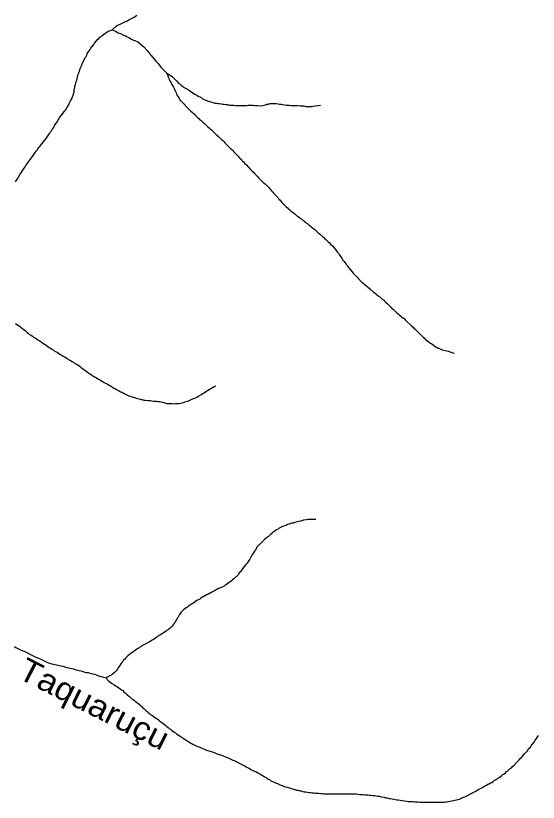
# Model space of a CAD drawing. Extents: x 652.3 to 678, y 7316.9 to 7344.9.
# Drawn here: x 664.343 to 666.148, y 7340.021 to 7342.739 of the extents above; entities that cross this region are included whole.
import ezdxf
from ezdxf.enums import TextEntityAlignment as Align

# ---------------------------------------------------------------- set-up
doc = ezdxf.new("R2010")
doc.units = 0
doc.header["$LTSCALE"] = 0.032
doc.layers.add('61', color=7, linetype='Continuous')
doc.layers.add('7', color=7, linetype='Continuous', lineweight=25)

msp = doc.modelspace()

# ---------------------------------------------------------------- linework, layer by layer
at = {"layer": '7'}
for points in [[(664.677, 7342.6909), (664.6898, 7342.7029), (664.6945, 7342.7061), (664.7017, 7342.7092), (664.7105, 7342.7132), (664.7152, 7342.7156), (664.72, 7342.718), (664.7248, 7342.7204), (664.7296, 7342.722), (664.7335, 7342.7252), (664.7526, 7342.7347), (664.7566, 7342.7379), (664.7614, 7342.7411)], [(664.3421, 7342.165), (664.3484, 7342.1745), (664.3516, 7342.1793), (664.354, 7342.1841), (664.3604, 7342.1936), (664.3635, 7342.1984), (664.3731, 7342.2127), (664.3755, 7342.2175), (664.3787, 7342.2215), (664.3818, 7342.2263), (664.385, 7342.231), (664.3914, 7342.239), (664.3978, 7342.2485), (664.4041, 7342.2565), (664.4105, 7342.266), (664.4137, 7342.2708), (664.4169, 7342.2748), (664.42, 7342.2788), (664.4232, 7342.2835), (664.4264, 7342.2875), (664.4296, 7342.2915), (664.4487, 7342.3154), (664.455, 7342.3249), (664.4614, 7342.3329), (664.4638, 7342.3377), (664.467, 7342.3416), (664.4694, 7342.3464), (664.4725, 7342.3512), (664.4757, 7342.3552), (664.4773, 7342.3599), (664.4805, 7342.3647), (664.4869, 7342.3727), (664.4893, 7342.3774), (664.4924, 7342.3822), (664.4948, 7342.387), (664.5076, 7342.4029), (664.5107, 7342.4077), (664.5147, 7342.4117), (664.5179, 7342.4164), (664.5203, 7342.4212), (664.5251, 7342.4307), (664.5282, 7342.4355), (664.5298, 7342.4403), (664.533, 7342.4451), (664.5378, 7342.4546), (664.5394, 7342.4594), (664.5418, 7342.4642), (664.5426, 7342.4697), (664.545, 7342.4745), (664.545, 7342.4801), (664.5458, 7342.4857), (664.5481, 7342.4904), (664.5481, 7342.496), (664.5497, 7342.5016), (664.5513, 7342.5063), (664.5521, 7342.5119), (664.5545, 7342.5167), (664.5553, 7342.5223), (664.5569, 7342.527), (664.5577, 7342.5326), (664.5593, 7342.5374), (664.5609, 7342.5421), (664.5633, 7342.5469), (664.5664, 7342.5565), (664.568, 7342.5612), (664.5704, 7342.566), (664.5736, 7342.5756), (664.576, 7342.5803), (664.5831, 7342.5947), (664.5863, 7342.5986), (664.5887, 7342.6034), (664.5903, 7342.6082), (664.5999, 7342.6225), (664.603, 7342.6273), (664.6062, 7342.6321), (664.6126, 7342.64), (664.6158, 7342.6448), (664.6221, 7342.6527), (664.6261, 7342.6567), (664.6301, 7342.6607), (664.6341, 7342.6647), (664.6381, 7342.6679), (664.642, 7342.671), (664.646, 7342.6742), (664.6508, 7342.6774), (664.6548, 7342.6806), (664.6587, 7342.6838), (664.6635, 7342.6862), (664.677, 7342.6909)], [(664.677, 7342.6909), (664.6882, 7342.6854), (664.6977, 7342.6806), (664.7049, 7342.6774), (664.716, 7342.6726), (664.7216, 7342.671), (664.7264, 7342.6679), (664.7359, 7342.6631), (664.7407, 7342.6599), (664.7502, 7342.6551), (664.755, 7342.6535), (664.7646, 7342.6488), (664.7693, 7342.6456), (664.7733, 7342.6424), (664.7773, 7342.6392), (664.7813, 7342.6352), (664.7853, 7342.6313), (664.7972, 7342.6193), (664.8004, 7342.6146), (664.8044, 7342.6106), (664.8075, 7342.6058), (664.8115, 7342.6018), (664.8274, 7342.5819), (664.8314, 7342.578), (664.8354, 7342.574), (664.8449, 7342.562), (664.8648, 7342.5413)], [(664.8648, 7342.5413), (664.8696, 7342.5286), (664.872, 7342.5238), (664.8736, 7342.5191), (664.876, 7342.5143), (664.8791, 7342.5095), (664.8823, 7342.5016), (664.8879, 7342.492), (664.8903, 7342.4872), (664.8927, 7342.4825), (664.8974, 7342.4729)], [(664.8648, 7342.5413), (664.8807, 7342.5318), (664.8847, 7342.5286), (664.8879, 7342.5246), (664.8919, 7342.5215), (664.8982, 7342.5143), (664.907, 7342.5055), (664.911, 7342.5024), (664.915, 7342.4992), (664.9189, 7342.496), (664.9229, 7342.4928), (664.9269, 7342.4896), (664.9364, 7342.4849), (664.9404, 7342.4817), (664.9452, 7342.4793), (664.95, 7342.4761), (664.9547, 7342.4729), (664.9595, 7342.4697), (664.9643, 7342.4673), (664.9691, 7342.4642), (664.9738, 7342.4618), (664.9786, 7342.4586), (664.9834, 7342.4562), (664.9874, 7342.453), (664.9921, 7342.4514), (665.0017, 7342.4467), (665.016, 7342.4419), (665.0216, 7342.4403), (665.0311, 7342.4371), (665.0367, 7342.4371), (665.0415, 7342.4355), (665.047, 7342.4355), (665.0582, 7342.4339), (665.0637, 7342.4339), (665.0693, 7342.4323), (665.0749, 7342.4323), (665.0797, 7342.4307), (665.0908, 7342.4307), (665.0964, 7342.43), (665.1019, 7342.4292), (665.1409, 7342.4292), (665.1465, 7342.43), (665.1632, 7342.43), (665.1688, 7342.4292), (665.1799, 7342.4292), (665.1911, 7342.4276), (665.1958, 7342.4292), (665.2014, 7342.43), (665.2062, 7342.4315), (665.2109, 7342.4331), (665.2165, 7342.4339), (665.2213, 7342.4355), (665.2436, 7342.4355), (665.2547, 7342.4339), (665.2603, 7342.4331), (665.2659, 7342.4323), (665.2714, 7342.4315), (665.277, 7342.4307), (665.2826, 7342.4307), (665.2881, 7342.43), (665.2937, 7342.4292), (665.316, 7342.4292), (665.3271, 7342.4276), (665.3383, 7342.4276), (665.3438, 7342.426), (665.3661, 7342.426), (665.3717, 7342.4268), (665.3772, 7342.4276), (665.3876, 7342.4292), (665.3955, 7342.4304), (665.3958, 7342.4304)], [(664.8974, 7342.4729), (664.899, 7342.4681), (664.9014, 7342.4634), (664.9078, 7342.4538), (664.9102, 7342.449), (664.9134, 7342.4451), (664.9253, 7342.4331), (664.9285, 7342.4292), (664.9325, 7342.4252), (664.9364, 7342.4212), (664.9484, 7342.4093), (664.9523, 7342.4061), (664.9563, 7342.4021), (664.9603, 7342.3989), (664.9643, 7342.3949), (664.9675, 7342.391), (664.9714, 7342.387), (664.9754, 7342.3838), (664.9794, 7342.3798), (664.9834, 7342.3766), (664.9874, 7342.3735), (664.9913, 7342.3695), (664.9953, 7342.3663), (664.9993, 7342.3631), (665.0073, 7342.3552), (665.0112, 7342.352), (665.0152, 7342.348), (665.0192, 7342.3448), (665.0271, 7342.3369), (665.0311, 7342.3337), (665.0343, 7342.3297), (665.0383, 7342.3265), (665.0423, 7342.3225), (665.0462, 7342.3194), (665.0542, 7342.3114), (665.0582, 7342.3082), (665.0622, 7342.3042), (665.0653, 7342.3003), (665.0852, 7342.2804), (665.0892, 7342.2772), (665.0932, 7342.2732), (665.0964, 7342.2692), (665.1043, 7342.2613), (665.1075, 7342.2573), (665.1115, 7342.2533), (665.1155, 7342.2493), (665.1186, 7342.2454), (665.1226, 7342.2422), (665.1258, 7342.2374), (665.1298, 7342.2342), (665.1338, 7342.2302), (665.1417, 7342.2223), (665.1449, 7342.2183), (665.1489, 7342.2143), (665.1521, 7342.2103), (665.16, 7342.2024), (665.164, 7342.1984), (665.168, 7342.1944), (665.1743, 7342.1865), (665.1783, 7342.1833), (665.1815, 7342.1793), (665.1974, 7342.1634), (665.2014, 7342.1602), (665.2054, 7342.157), (665.2173, 7342.1451), (665.2205, 7342.1411), (665.2245, 7342.1371), (665.2277, 7342.1332), (665.2316, 7342.1292), (665.2348, 7342.1252), (665.2428, 7342.1172), (665.246, 7342.1133), (665.2491, 7342.1093), (665.2523, 7342.1053), (665.2563, 7342.1013), (665.2627, 7342.0934), (665.2666, 7342.0894), (665.2706, 7342.0862), (665.2738, 7342.0822), (665.2778, 7342.0783), (665.2818, 7342.0751), (665.2857, 7342.0711), (665.2897, 7342.0679), (665.2937, 7342.0647), (665.2985, 7342.0615), (665.3025, 7342.0584), (665.3064, 7342.0552), (665.3104, 7342.0512), (665.3144, 7342.048), (665.3192, 7342.0448), (665.3231, 7342.0417), (665.3279, 7342.0385), (665.3319, 7342.0353), (665.3359, 7342.0321), (665.3398, 7342.0289), (665.3438, 7342.0257), (665.3478, 7342.0226), (665.3518, 7342.0194), (665.3558, 7342.0162), (665.3597, 7342.013), (665.3637, 7342.0098)], [(665.3637, 7342.0098), (665.3677, 7342.0066), (665.3717, 7342.0035), (665.3757, 7342.0003), (665.3796, 7341.9971), (665.3876, 7341.9891), (665.3916, 7341.986), (665.3955, 7341.9828), (665.3995, 7341.9796), (665.4035, 7341.9756), (665.4075, 7341.9724), (665.4107, 7341.9685), (665.4146, 7341.9653), (665.4226, 7341.9573), (665.4266, 7341.9541), (665.4306, 7341.9502), (665.4385, 7341.9422), (665.4544, 7341.9223), (665.4576, 7341.9183), (665.4608, 7341.9136), (665.4703, 7341.8992), (665.4735, 7341.8945), (665.4767, 7341.8905), (665.4799, 7341.8865), (665.4831, 7341.8817), (665.4863, 7341.8777), (665.4894, 7341.8738), (665.5085, 7341.8499), (665.5125, 7341.8459), (665.5165, 7341.8419), (665.5197, 7341.838), (665.5237, 7341.8348), (665.5268, 7341.83), (665.5388, 7341.8181), (665.5427, 7341.8149), (665.5467, 7341.8109), (665.5515, 7341.8077), (665.5555, 7341.8045), (665.5595, 7341.8006), (665.5634, 7341.7974), (665.5674, 7341.7934), (665.5714, 7341.7902), (665.5754, 7341.787), (665.5794, 7341.7839), (665.5841, 7341.7807), (665.5881, 7341.7767), (665.5921, 7341.7735), (665.5961, 7341.7703), (665.6008, 7341.7671), (665.6048, 7341.7632), (665.6088, 7341.76), (665.6128, 7341.7568), (665.6167, 7341.7528), (665.6207, 7341.7496), (665.6247, 7341.7457), (665.6287, 7341.7425), (665.6366, 7341.7345), (665.6398, 7341.7305), (665.6438, 7341.7266), (665.6478, 7341.7234), (665.6557, 7341.7154), (665.6597, 7341.7122), (665.6637, 7341.7091), (665.6677, 7341.7051), (665.6717, 7341.7019), (665.6756, 7341.6987), (665.6796, 7341.6955), (665.6844, 7341.6923), (665.6884, 7341.6884), (665.6915, 7341.6844), (665.6955, 7341.6812), (665.7075, 7341.6693), (665.7114, 7341.6661), (665.7154, 7341.6629), (665.7186, 7341.6589), (665.7226, 7341.6557), (665.7425, 7341.6359), (665.7464, 7341.6319), (665.7504, 7341.6279), (665.7544, 7341.6247), (665.7584, 7341.6207), (665.7624, 7341.6176), (665.7663, 7341.6144), (665.7703, 7341.6112), (665.7751, 7341.608), (665.7799, 7341.6048), (665.7846, 7341.6016), (665.7886, 7341.5985), (665.7926, 7341.5953), (665.7974, 7341.5937), (665.8021, 7341.5905), (665.8069, 7341.5889), (665.8117, 7341.5865), (665.8165, 7341.5849), (665.8212, 7341.5833), (665.8268, 7341.5825), (665.8316, 7341.581), (665.8364, 7341.5794), (665.8523, 7341.5746), (665.8568, 7341.5732), (665.8572, 7341.5731)], [(664.3413, 7341.6756), (664.346, 7341.6733), (664.3508, 7341.6701), (664.3556, 7341.6669), (664.3596, 7341.6637), (664.3635, 7341.6605), (664.3675, 7341.6573), (664.3715, 7341.6542), (664.3755, 7341.651), (664.3795, 7341.6478), (664.3834, 7341.6446), (664.3874, 7341.6406), (664.3914, 7341.6374), (664.3962, 7341.6351), (664.4009, 7341.6319), (664.4049, 7341.6287), (664.4145, 7341.6239), (664.4184, 7341.6207), (664.4224, 7341.6176), (664.4272, 7341.6152), (664.4312, 7341.612), (664.4359, 7341.6088), (664.4407, 7341.6056), (664.4455, 7341.6024), (664.4495, 7341.5993), (664.4542, 7341.5961), (664.459, 7341.5929), (664.463, 7341.5897), (664.4678, 7341.5865), (664.4725, 7341.5841), (664.4765, 7341.581), (664.4813, 7341.5786), (664.4861, 7341.5762)], [(664.4861, 7341.5762), (664.4908, 7341.573), (664.4956, 7341.5698), (664.5004, 7341.5666), (664.5052, 7341.5634), (664.5147, 7341.5587), (664.5195, 7341.5555), (664.5235, 7341.5523), (664.533, 7341.5475), (664.5378, 7341.5444), (664.5426, 7341.542), (664.5465, 7341.5388), (664.5513, 7341.5364), (664.5561, 7341.5332), (664.5609, 7341.53), (664.5656, 7341.5268), (664.5696, 7341.5237), (664.5736, 7341.5205), (664.5776, 7341.5173), (664.5816, 7341.5141), (664.5863, 7341.5109), (664.5911, 7341.5077), (664.5951, 7341.5038), (664.5999, 7341.5014), (664.6046, 7341.4982), (664.6086, 7341.495), (664.6134, 7341.4934), (664.6174, 7341.4902), (664.6221, 7341.4879), (664.6269, 7341.4847), (664.6317, 7341.4815), (664.6365, 7341.4791), (664.6404, 7341.4759), (664.6452, 7341.4743), (664.6492, 7341.4711), (664.6587, 7341.4664), (664.6635, 7341.4632), (664.6731, 7341.4584), (664.6778, 7341.4552), (664.6818, 7341.4521), (664.6866, 7341.4505), (664.6914, 7341.4473), (664.6961, 7341.4449), (664.7009, 7341.4425), (664.7057, 7341.4393), (664.7105, 7341.4377), (664.7152, 7341.4345), (664.72, 7341.4322), (664.7248, 7341.4298), (664.7296, 7341.4282), (664.7343, 7341.4258), (664.7487, 7341.421), (664.7542, 7341.4194), (664.759, 7341.4178), (664.7638, 7341.4162), (664.7693, 7341.4147), (664.7749, 7341.4131), (664.7805, 7341.4123), (664.7853, 7341.4107), (664.7908, 7341.4107), (664.802, 7341.4091), (664.8075, 7341.4091), (664.8131, 7341.4083), (664.8187, 7341.4075), (664.8298, 7341.4075), (664.8346, 7341.4059), (664.8402, 7341.4059), (664.8457, 7341.4051), (664.8505, 7341.4035), (664.8561, 7341.4019), (664.8608, 7341.4003), (664.8664, 7341.3995), (664.872, 7341.3995), (664.8776, 7341.3987), (664.8839, 7341.3987), (664.8895, 7341.3979), (664.8951, 7341.3987), (664.9014, 7341.3987), (664.907, 7341.3995), (664.9126, 7341.4003), (664.9181, 7341.4011), (664.9229, 7341.4027), (664.9277, 7341.4043), (664.9372, 7341.4075), (664.9428, 7341.4091), (664.9571, 7341.4162), (664.9619, 7341.4178), (664.9667, 7341.4202), (664.9714, 7341.4218), (664.9754, 7341.425), (664.985, 7341.4298), (664.9897, 7341.433), (664.9945, 7341.4361), (664.9993, 7341.4393), (665.0033, 7341.4425), (665.008, 7341.4449), (665.012, 7341.4481), (665.0168, 7341.4505), (665.0311, 7341.4584), (665.0339, 7341.46), (665.0343, 7341.4602)], [(665.3796, 7340.9985), (665.3589, 7340.9985), (665.3534, 7340.9977), (665.3478, 7340.9969), (665.3367, 7340.9953), (665.3271, 7340.9921), (665.3215, 7340.9913), (665.312, 7340.9882), (665.3064, 7340.9874), (665.3017, 7340.9858), (665.2961, 7340.985), (665.2865, 7340.9818), (665.2818, 7340.9802), (665.277, 7340.9778), (665.2722, 7340.9762), (665.2674, 7340.9746), (665.2579, 7340.9699), (665.2531, 7340.9683), (665.2491, 7340.9651), (665.2444, 7340.9627), (665.2404, 7340.9595), (665.2356, 7340.9563), (665.2316, 7340.9532), (665.2277, 7340.95), (665.2237, 7340.946), (665.2197, 7340.9428), (665.2157, 7340.9396), (665.2117, 7340.9364), (665.2078, 7340.9333), (665.2038, 7340.9301), (665.1879, 7340.9142), (665.1839, 7340.911), (665.1775, 7340.903), (665.1712, 7340.8935), (665.168, 7340.8887), (665.1616, 7340.8792), (665.1584, 7340.8752), (665.1537, 7340.8656), (665.1513, 7340.8609)], [(665.1513, 7340.8609), (665.1489, 7340.8561), (665.1425, 7340.8465), (665.1385, 7340.8426), (665.1258, 7340.8266), (665.1194, 7340.8171), (665.1155, 7340.8131), (665.1123, 7340.8083), (665.0964, 7340.7924), (665.0924, 7340.7892), (665.0884, 7340.7861), (665.0844, 7340.7829), (665.0805, 7340.7797), (665.0757, 7340.7765), (665.0717, 7340.7733), (665.0669, 7340.7709), (665.0629, 7340.7678), (665.0486, 7340.7606), (665.0439, 7340.759), (665.0295, 7340.7518), (665.0256, 7340.7487), (665.0208, 7340.7471), (665.016, 7340.7439), (665.0112, 7340.7423), (665.0065, 7340.7391), (665.0017, 7340.7375), (664.9969, 7340.7343), (664.9921, 7340.7312), (664.9874, 7340.7296), (664.9826, 7340.7264), (664.9786, 7340.7232), (664.9738, 7340.7208), (664.9691, 7340.7176), (664.9643, 7340.7144), (664.9595, 7340.7113), (664.9547, 7340.7081), (664.95, 7340.7049), (664.9452, 7340.7017), (664.9404, 7340.6985), (664.9364, 7340.6954), (664.9325, 7340.6922), (664.9277, 7340.689), (664.9229, 7340.6858), (664.915, 7340.6778), (664.9086, 7340.6699), (664.907, 7340.6651), (664.9038, 7340.6603), (664.9006, 7340.6564), (664.8982, 7340.6516), (664.8951, 7340.6468), (664.8927, 7340.642), (664.8895, 7340.6373), (664.8863, 7340.6333), (664.8831, 7340.6285), (664.8791, 7340.6245), (664.8752, 7340.6214), (664.8712, 7340.6182), (664.8664, 7340.615), (664.8624, 7340.6118), (664.8577, 7340.6086), (664.8529, 7340.6054), (664.8481, 7340.6023), (664.8433, 7340.5999), (664.8394, 7340.5967), (664.8346, 7340.5943), (664.8306, 7340.5911), (664.8258, 7340.5879), (664.8211, 7340.5848), (664.8171, 7340.5816), (664.8123, 7340.5792), (664.8075, 7340.5768), (664.8028, 7340.5736), (664.7932, 7340.5688), (664.7884, 7340.5657), (664.7837, 7340.5641), (664.7789, 7340.5609), (664.7749, 7340.5577), (664.7701, 7340.5553), (664.7662, 7340.5521), (664.7614, 7340.5497), (664.7574, 7340.5466), (664.7526, 7340.5434), (664.7487, 7340.5402), (664.7439, 7340.537), (664.7391, 7340.5338), (664.7351, 7340.5298), (664.7311, 7340.5267), (664.7272, 7340.5235), (664.7232, 7340.5195), (664.72, 7340.5155), (664.716, 7340.5123), (664.7136, 7340.5076), (664.7097, 7340.5036), (664.7065, 7340.4996), (664.7001, 7340.4901), (664.6969, 7340.4853), (664.6945, 7340.4805), (664.6914, 7340.4765), (664.685, 7340.4694), (664.6754, 7340.4614), (664.6548, 7340.4503)], [(664.3397, 7340.5593), (664.3436, 7340.5561), (664.3484, 7340.5537), (664.3532, 7340.5505), (664.358, 7340.5489), (664.3675, 7340.5442), (664.3723, 7340.5426), (664.4009, 7340.5283), (664.4057, 7340.5259), (664.4153, 7340.5211), (664.42, 7340.5195), (664.4296, 7340.5147), (664.4344, 7340.5131), (664.4535, 7340.5036), (664.463, 7340.5004), (664.4678, 7340.4988), (664.4733, 7340.498), (664.4789, 7340.4964), (664.4845, 7340.4956), (664.4893, 7340.494), (664.5004, 7340.4925), (664.506, 7340.4909), (664.5155, 7340.4877), (664.5211, 7340.4869), (664.5267, 7340.4853), (664.5314, 7340.4837), (664.537, 7340.4829), (664.5426, 7340.4813), (664.5473, 7340.4797), (664.5521, 7340.4781), (664.5577, 7340.4773), (664.5625, 7340.4757), (664.568, 7340.4749), (664.5728, 7340.4734), (664.5824, 7340.4702), (664.5879, 7340.4694), (664.5935, 7340.4686), (664.5991, 7340.467), (664.6038, 7340.4654), (664.6094, 7340.4646), (664.615, 7340.463), (664.6245, 7340.4598), (664.6293, 7340.4582), (664.6388, 7340.4551), (664.6548, 7340.4503)], [(664.6548, 7340.4503), (664.6651, 7340.4391), (664.6699, 7340.436), (664.6747, 7340.4328), (664.6818, 7340.428), (664.6906, 7340.4224), (664.6953, 7340.4192), (664.6993, 7340.4161), (664.7041, 7340.4129)], [(664.7041, 7340.4129), (664.7081, 7340.4097), (664.7128, 7340.4065), (664.7168, 7340.4025), (664.7208, 7340.3986), (664.7248, 7340.3954), (664.7288, 7340.3922), (664.7327, 7340.389), (664.7367, 7340.3858), (664.7407, 7340.3819), (664.7447, 7340.3787), (664.7494, 7340.3755), (664.7534, 7340.3723), (664.7574, 7340.3691), (664.7614, 7340.3659), (664.7654, 7340.3628), (664.7693, 7340.3596), (664.7733, 7340.3556), (664.7773, 7340.3524), (664.7813, 7340.3484), (664.7853, 7340.3452), (664.7892, 7340.3413), (664.7932, 7340.3373), (664.7972, 7340.3341), (664.8012, 7340.3309), (664.8051, 7340.3269), (664.8091, 7340.3238), (664.8139, 7340.3214), (664.8179, 7340.3182), (664.8227, 7340.315), (664.8274, 7340.3118), (664.8314, 7340.3086), (664.8362, 7340.3055), (664.8402, 7340.3023), (664.8441, 7340.2991), (664.8481, 7340.2959), (664.8529, 7340.2927), (664.8569, 7340.2896), (664.8616, 7340.2864), (664.8656, 7340.2824), (664.8696, 7340.2792), (664.8736, 7340.276), (664.8776, 7340.2728), (664.8815, 7340.2697), (664.8855, 7340.2665), (664.8903, 7340.2633), (664.8951, 7340.2601), (664.899, 7340.2569), (664.9038, 7340.2537), (664.9086, 7340.2506), (664.9134, 7340.2474), (664.9173, 7340.2442), (664.9221, 7340.2418), (664.9261, 7340.2386), (664.9309, 7340.2362), (664.9356, 7340.2331), (664.9404, 7340.2307), (664.9452, 7340.2275), (664.95, 7340.2243), (664.9691, 7340.2148), (664.9786, 7340.2116), (664.9882, 7340.2068), (664.9929, 7340.2052), (664.9977, 7340.2028), (665.0025, 7340.2012), (665.0073, 7340.1996), (665.0216, 7340.1949), (665.0263, 7340.1933), (665.0311, 7340.1917), (665.0359, 7340.1893), (665.0454, 7340.1861), (665.0502, 7340.1845), (665.0598, 7340.1813), (665.0645, 7340.179), (665.0693, 7340.1774), (665.0741, 7340.175), (665.0789, 7340.1734), (665.0932, 7340.1662), (665.098, 7340.1646), (665.1266, 7340.1503), (665.1314, 7340.1479), (665.1362, 7340.1455), (665.1409, 7340.1423), (665.1505, 7340.1376), (665.1552, 7340.1344), (665.1696, 7340.1272), (665.1743, 7340.1256), (665.1791, 7340.1225), (665.1887, 7340.1177), (665.1934, 7340.1145), (665.1982, 7340.1121), (665.2022, 7340.1089), (665.207, 7340.1073), (665.2109, 7340.1042), (665.2149, 7340.101), (665.2197, 7340.0994), (665.2237, 7340.0962), (665.2428, 7340.0867), (665.2475, 7340.0851), (665.2523, 7340.0827), (665.2571, 7340.0811)], [(666.0257, 7340.1161), (666.0297, 7340.1193), (666.0345, 7340.1225), (666.0385, 7340.1264), (666.0432, 7340.1296), (666.0472, 7340.1336), (666.0512, 7340.1368), (666.0552, 7340.14), (666.0592, 7340.1439), (666.0631, 7340.1479), (666.0751, 7340.1599), (666.0782, 7340.1638), (666.0822, 7340.1678), (666.0854, 7340.1718), (666.0894, 7340.1758), (666.0934, 7340.1797), (666.0997, 7340.1877), (666.1037, 7340.1909), (666.1069, 7340.1949), (666.1101, 7340.1988), (666.1133, 7340.2036), (666.1164, 7340.2076), (666.1204, 7340.2116), (666.1236, 7340.2156), (666.1268, 7340.2203), (666.1332, 7340.2283), (666.1363, 7340.2331), (666.1395, 7340.2378), (666.1459, 7340.2474), (666.1483, 7340.2522)], [(665.2571, 7340.0811), (665.2619, 7340.0787), (665.2714, 7340.0755), (665.2762, 7340.0739), (665.281, 7340.0723), (665.2921, 7340.0691), (665.2977, 7340.0676), (665.3032, 7340.066), (665.3128, 7340.0628), (665.3184, 7340.062), (665.3239, 7340.0604), (665.3295, 7340.0596), (665.3343, 7340.058), (665.3398, 7340.0572), (665.3454, 7340.0564), (665.351, 7340.0556), (665.3574, 7340.0548), (665.3629, 7340.0548), (665.3685, 7340.0532), (665.3741, 7340.0532), (665.3788, 7340.0516), (665.39, 7340.0516), (665.3955, 7340.0508), (665.4011, 7340.0508), (665.4075, 7340.05), (665.4131, 7340.0493), (665.5189, 7340.0493), (665.5244, 7340.0485), (665.53, 7340.0477), (665.5364, 7340.0477), (665.542, 7340.0469), (665.5475, 7340.0461), (665.5587, 7340.0461), (665.5642, 7340.0453), (665.5698, 7340.0453), (665.5754, 7340.0445), (665.5825, 7340.0437), (665.5881, 7340.0429), (665.5945, 7340.0413), (665.6, 7340.0413), (665.6048, 7340.0397), (665.616, 7340.0381), (665.6207, 7340.0365), (665.6263, 7340.0357), (665.6319, 7340.0341), (665.6374, 7340.0333), (665.6486, 7340.0317), (665.6534, 7340.0302), (665.6589, 7340.0294), (665.6645, 7340.0286), (665.6709, 7340.0278), (665.6764, 7340.027), (665.6876, 7340.0254), (665.6931, 7340.0246), (665.6987, 7340.0238), (665.7098, 7340.0238), (665.7162, 7340.023), (665.7218, 7340.0222), (665.7329, 7340.0222), (665.7385, 7340.0214), (665.7608, 7340.0214), (665.7663, 7340.0206), (665.8165, 7340.0206), (665.822, 7340.0214), (665.8276, 7340.0222), (665.8332, 7340.0222), (665.838, 7340.0238), (665.8435, 7340.0246), (665.8491, 7340.0254), (665.8547, 7340.0262), (665.8594, 7340.0278), (665.865, 7340.0286), (665.8698, 7340.0302), (665.8753, 7340.0317), (665.8849, 7340.0365), (665.8897, 7340.0381), (665.8944, 7340.0397), (665.8992, 7340.0421), (665.9231, 7340.054), (665.9279, 7340.0572), (665.9326, 7340.0588), (665.9366, 7340.062), (665.9414, 7340.0652), (665.9462, 7340.0668), (665.9509, 7340.0699), (665.9557, 7340.0715), (665.9597, 7340.0747), (665.9692, 7340.0795), (665.9732, 7340.0827), (665.978, 7340.0843), (665.9828, 7340.0874), (665.9875, 7340.089), (665.9915, 7340.0922), (665.9955, 7340.0954), (666.0003, 7340.0978), (666.0042, 7340.101), (666.0082, 7340.1042), (666.013, 7340.1065), (666.0178, 7340.1097), (666.0218, 7340.1129), (666.0257, 7340.1161)]]:
    msp.add_lwpolyline(points, dxfattribs=at)

# ---------------------------------------------------------------- texts
at = {"layer": '61', "width": 1.1}
msp.add_text('Taquaruçu', height=0.08, rotation=333.094, dxfattribs=at).set_placement((664.5966, 7340.3248), align=Align.CENTER)

doc.saveas('drawing.dxf')
